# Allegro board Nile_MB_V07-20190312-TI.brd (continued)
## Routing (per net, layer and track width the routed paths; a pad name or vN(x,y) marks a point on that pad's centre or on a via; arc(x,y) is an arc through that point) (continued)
VREG_HUB_3P3: length 46.5
  INNER LAYER 3 w0.3: v3(7.98,11.68) 9.68,11.68 v3(9.83,11.53)
  INNER LAYER 5 w0.3: v3(16.63,12.08) 16.63,12.18 15.61,12.18 15.23,11.8 15.11,11.8 15.11,11.8 14.76,11.8 14.72,11.76 14.46,11.76 13.93,11.23 10.38,11.23 10.08,11.53 v3(9.83,11.53)
  INNER LAYER 8 w0.25: 9.63,11.58 9.63,12.05 9.63,12.05 9.63,12.65 9.71,12.73 9.71,13.26 10.06,13.61 10.06,13.66 v1(10.28,13.88) ; 9.71,11.08 9.71,10.83 9.58,10.71 v1(9.58,10.42)
  INNER LAYER 8 w0.3: v1(15.98,15.18) 15.63,14.83 15.02,14.83 v1(14.15,13.96) 13.73,14.38 v1(11.78,14.38) ; v3(7.98,11.68) 7.83,11.83 7.83,12.41 9.33,13.91 9.33,14.43 v1(9.78,14.88) ; v2(10.83,15.88) 10.88,15.88 10.96,15.96 10.96,15.99 11.68,16.71 v1(11.68,17.78) ; v3(16.63,12.08) 16.58,12.03 v1(16.58,11.63) ; 9.63,11.58 9.68,11.53 v3(9.83,11.53) 9.71,11.41 9.71,11.08
  INNER LAYER 9 w0.22: v1(10.28,16.38) 10.78,15.88 v2(10.83,15.88)
  INNER LAYER 9 w0.3: v1(13.33,17.83) 13.33,17.93 12.98,18.28 11.85,18.28 v1(11.83,18.27) 12.03,18.07 12.03,17.23 11.28,16.48 v1(11.28,16.38) ; v1(9.38,18.27) 9.38,18.43 9.6,18.65 11.02,18.65 11.23,18.43 v1(11.23,18.27)
  BOTTOM w0.076: 16,13.91 15.97,13.94 R6683.1 ; 16,13.31 15.97,13.34 R6679.1 ; 16,12.73 16,12.78 15.97,12.76 R6686.2 ; R6690.2 8.78,18.9 ; 16,15.18 v1(15.98,15.18) R6680.1 ; R6676.2 15.97,14.57 16,14.54 ; 16,12.14 15.97,12.17 R6684.1 ; R6689.2 15.98,15.77 ; R479.2 16,11.48
  BOTTOM w0.15: 8.78,18.9 8.83,18.9 9.06,18.67 9.06,18.63 9.06,18.63 9.06,18.58 9.11,18.53 9.11,18.46 9.3,18.27 v1(9.38,18.27)
  BOTTOM w0.22: v1(9.38,18.27) 9.38,17.88 9.78,17.48 U6838.A7
  BOTTOM w0.3: 16,12.78 16,15.18 ; v1(13.33,17.83) 13.76,17.41 13.76,17.09 14.12,16.73 B33.1 14.83,16.73 14.9,16.8 14.9,16.7 15.2,16.4 ; 15.2,16.4 15.62,16.4 16,16.02 16,15.78 15.98,15.77 v1(15.98,15.18) ; 15.2,16.4 15.17,16.4 15.03,16.53 15.03,16.94 C6370.1 ; B32.2 v1(16.58,11.63) 16.15,11.63 16,11.48 16,12.73 ; v1(11.68,17.78) 11.83,17.93 v1(11.83,18.27) v1(11.23,18.27)
VREG_L3A_1P3: length 16.9
  INNER LAYER 8 w0.3: 23.64,16.4 v1(23.73,16.49) 23.74,16.49 23.88,16.63 ; 23.64,16.4 23.54,16.3 v1(23.54,16.25) ; 23.64,16.4 v1(23.27,16.4)
  INNER LAYER 8 w0.6: 35.37,10.9 32.51,13.76 32.51,15.81 30.75,17.58 24.51,17.58 23.88,16.95 23.88,16.63
VREG_L7A_0P8:
  vias: v7(54.79,29.46) v12(54.9,29.17) v12(55.15,29.18) v12(55.39,29.19)
VREG_L8A_1P8: length 29.9
  TOP w0.2: v5(39,27.96) 39.5,27.46
  TOP w0.25: 38.5,27.96 v5(39,27.96)
  TOP w0.3: v6(38,24.46) v6(38.5,24.46) v6(39,24.46)
  TOP w0.305: v6(39,24.96) v6(39,24.46) ; 39.5,27.46 40,27.46
  INNER LAYER 2 w0.3: v6(37.91,28.26) 38.2,28.26 v5(38.5,27.96)
  INNER LAYER 2 w0.5: v5(39,27.96) 38.52,27.96 v6(38.47,27.92)
  INNER LAYER 3 w0.3: v3(37.67,24.62) 37.83,24.46 v6(38,24.46) ; 37.51,28.26 v6(37.91,28.26) 37.91,28.12 38.11,27.92 ; 37.51,28.26 37.51,28.26 v3(37.41,28.36) ; 37.51,28.26 37.85,27.92 38.11,27.92 ; 38.11,27.92 v6(38.47,27.92) ; v6(38,24.46) 37.89,24.35 v3(37.89,24.15) ; v6(38,24.46) v6(38.5,24.46) ; v6(39,24.96) v6(39,24.46)
  INNER LAYER 7 w0.5: v3(37.89,24.15) 37.89,24.4 v3(37.67,24.62) 37.24,24.62 36.79,25.07 36.79,27.19 36.94,27.34 36.94,27.71 37.41,28.18 v3(37.41,28.36)
  INNER LAYER 7 w0.6: v3(37.41,28.36) 37.41,28.66 37.27,28.8 37.27,34.64 37.28,34.65 37.28,35.29 41.31,39.32
  INNER LAYER 8 w0.3: v3(37.67,24.62) 37.67,24.5 v1(37.49,24.31) 37.73,24.31 v3(37.89,24.15) 38.11,24.37 v1(38.35,24.37)
  INNER LAYER 8 w0.5: v3(37.41,28.36) 37.46,28.31 37.46,27.85 v1(37.5,27.82)
  BOTTOM w0.076: C128.1 38.37,27.84
  BOTTOM w0.3: v1(37.5,27.82) 38.35,27.82 38.37,27.84 ; v1(38.35,24.37) 37.55,24.37 v1(37.49,24.31)
VREG_L9A_1P8: length 64.5
  INNER LAYER 5 w0.25: v3(18.36,41.88) 18.66,41.58 19.53,41.58 19.71,41.41 31.95,41.41 32.26,41.72 39.57,41.72 39.97,42.13
  INNER LAYER 6 w0.127: v7(25.71,10.85) 25.4,10.54 24.8,10.54 24.64,10.38 21.98,10.38 21.98,10.38 v7(21.08,10.38)
  INNER LAYER 7 w0.25: v7(21.23,14.32) 21.23,14.6 21.66,15.03 21.66,33.56 18.63,36.6 18.63,41.69 18.43,41.88 v3(18.36,41.88)
  INNER LAYER 8 w0.127: v7(25.71,10.85) 25.82,10.96 25.83,10.96 25.83,10.61 v8(25.8,10.59)
  INNER LAYER 8 w0.25: v1(21.45,10.38) v7(21.08,10.38)
  INNER LAYER 8 w0.3: v1(21,14.01) 21.23,14.24 v7(21.23,14.32)
  INNER LAYER 9 w0.25: v1(21.68,16.46) 21.42,16.46 v1(20.89,15.93)
  BOTTOM w0.064: U18.32 25.81,10.59 v8(25.8,10.59)
  BOTTOM w0.25: v1(20.89,15.93) 20.89,14.13 v1(21,14.01) 21,13.97 20.95,13.92 20.95,12.32 21.16,12.11 21.16,12.08 21.28,11.96 21.31,11.96 21.53,11.74 C269.1
  BOTTOM w0.4: v1(21.45,10.38) 21.34,10.49 21.58,10.74 C269.1
VREG_L10A_1P8_RES:
  vias: v7(56.75,30.51) v7(57.01,30.76) v7(57.28,30.51) v8(57.63,30.38) v8(57.84,30.3)
VREG_L13A_1P8: length 71
  TOP w0.076: 39.1,17.9 39.11,17.88 C122.1
  TOP w0.25: 39,20.46 39,19.81 39.54,19.27 39.54,18.09 39.74,17.9 39.1,17.9 38.5,18.49 38.5,20.46 ; 39,31.46 39,32.76 39.91,33.66 v6(39.91,34.65) v6(39.25,34.65) 39.25,33.57 38.5,32.83 38.5,31.96
  TOP w0.3: 39.3,34.66 39.9,34.66 v6(39.91,34.65) ; 39.74,17.9 39.74,17.81 v6(39.74,17.8)
  TOP w0.305: 39,20.96 39,20.46
  INNER LAYER 3 w0.3: v6(39.74,17.8) 39.74,17.9 40.14,18.3 40.52,18.3 41.89,19.67
  INNER LAYER 3 w0.35: v6(39.25,34.65) 39.25,34.48 v7(39.4,34.32) ; v6(39.91,34.65) v7(39.91,34.3)
  INNER LAYER 4 w0.3: v7(47.1,34) 47.1,34 ; 47.1,34 47.09,33.99 ; 47.1,34 47.09,34 46.87,34.22 v3(46.87,34.25)
  INNER LAYER 5 w0.3: v7(39.4,34.32) 39.42,34.3 v7(39.91,34.3) ; v3(22.1,11.72) 22.5,12.12 22.5,14.12 23.73,15.35 26.37,15.35 27.81,13.91 v7(27.91,13.91)
  INNER LAYER 5 w0.5: 41.69,33.97 41.63,33.9 40.31,33.9 v7(39.91,34.3)
  INNER LAYER 6 w0.5: v7(39.4,34.32) 39.42,34.3 v7(39.91,34.3)
  INNER LAYER 7 w0.3: v7(39.4,34.32) 39.81,33.92 ; 39.91,33.92 v7(39.91,34.3)
  INNER LAYER 7 w0.5: 39.81,33.92 39.91,33.92
  INNER LAYER 8 w0.25: v1(27.65,13.62) 27.65,13.65 v7(27.91,13.91)
  INNER LAYER 8 w0.3: v1(22.39,11.72) v3(22.1,11.72) ; 46.78,34.31 46.78,34.32 ; v2(18.73,12.68) 18.76,12.68 18.91,12.53 18.91,10.01 v1(18.08,9.18) ; v1(41.61,23.3) 41.44,23.47 40.42,23.47 40.12,23.77 39.32,23.77 39.17,23.92 38.96,23.92 38.77,23.73 37.72,23.73 37.7,23.76 v2(36.21,23.76)
  INNER LAYER 8 w0.5: 41.61,23.29 v1(41.61,23.3)
  INNER LAYER 9 w0.3: v2(36.21,23.76) 36.05,23.6 34.39,23.6 v8(34.36,23.57) ; v1(29.03,15.65) 29.03,15.92 v1(29.02,15.93) 29.02,15.95 29,15.97 ; v1(22.39,11.72) 22.39,11.71 21.96,11.71 21.83,11.57 21.4,11.57 20.66,12.32 19.66,12.32 19.56,12.42 19.01,12.42 18.82,12.61 18.82,12.68 v2(18.73,12.68) 18.73,12.68 v1(18.28,12.68)
  INNER LAYER 9 w0.4: 29,15.97 28.89,16.08 29.89,17.08 30.24,17.08 30.27,17.12 30.58,17.12 30.74,16.96 31.46,16.96 31.83,16.59 32.42,16.59 32.69,16.86 34.41,16.86 35.26,17.71 35.26,22.06 34.81,22.51 34.81,23.11 v8(34.36,23.57)
  BOTTOM w0.076: 26.83,12.1 26.8,12.13
  BOTTOM w0.178: U18.56 26.83,12.1
  BOTTOM w0.2: U18.56 26.83,12.3 26.81,12.32
  BOTTOM w0.3: v8(34.36,23.57) 34.22,23.43 32.14,23.43 31.82,23.75 U11.5 ; 26.81,12.32 26.81,12.41 27.65,13.25 v1(27.65,13.62) 27.8,13.62 28.07,13.88 28.07,13.89 28.29,14.11 28.3,14.11 28.97,14.79 28.97,15.36
  BOTTOM w0.4: 28.97,15.36 29.01,15.39 C262.1
VREG_L19A_3P0: length 13.2
  INNER LAYER 3 w0.3: v6(38,26.96) v6(38,26.46) v6(38,25.96) 37.72,25.96 37.45,26.23 v3(37.45,26.43)
  INNER LAYER 3 w0.5: v3(37.71,27.15) 37.9,26.96 v6(38,26.96)
  INNER LAYER 8 w0.5: v3(37.45,26.43) 37.47,26.45 v1(37.47,26.83) 37.47,26.91 v3(37.71,27.15)
  INNER LAYER 8 w0.6: 40.35,39.34 39.73,38.72 v1(39.03,38.72)
  BOTTOM w0.3: C124.1 37.5,26.82 v1(37.5,25.9) ; C124.1 v1(37.47,26.83) ; C124.1 37.63,26.97 v1(38.33,26.97) ; 39.02,35.34 38.44,35.34 38.33,35.23 ; 39.03,37.84 39.06,37.81 39.06,36.71 38.33,35.97
  BOTTOM w0.5: 38.33,34.87 v1(38.33,33.01)
  BOTTOM w0.6: v1(39.03,38.72) 39.03,37.84 ; 38.33,34.87 38.33,35.97
  vias: v1(37.96,33.28) v1(37.96,32.98) v1(37.99,26.95) v1(38.01,26.59) v1(37.92,26.26) v1(38.31,33.31) v1(38.7,38.92) v1(38.69,33.32) v1(38.66,33) v1(38.74,38.49) v1(39,39.15) v1(39.1,38.35) v1(39.03,33.28) v1(39.02,33.01) v1(39.39,39.19) v1(39.47,38.87) v1(39.44,38.53) v2(37.99,26.95) v2(38.01,26.59) v2(37.92,26.26) v2(38.7,38.92) v2(38.74,38.49) v2(39,39.15) v2(39.1,38.35) v2(39.39,39.19) v2(39.47,38.87) v2(39.44,38.53)
VREG_S1C_S4C_0P752: length 3
  BOTTOM w0.3: C232.1 36.99,21.59
  BOTTOM w1: 29.16,20.84 30.67,20.84 30.78,20.74 32.08,20.74
VREG_S2C_1P125: length 55.4
  TOP w0.076: 41.62,17.86 41.65,17.83 v6(41.65,17.78) ; 41.42,19.98 41.42,19.92 ; 41.95,25.46 42,25.46
  TOP w0.2: 41.2,32.34 v6(41.2,34.65) ; 41.12,31.46 42,31.46 ; 40,31.46 40.33,31.46
  TOP w0.25: v6(41.82,34.65) 41.82,33.36 41.57,33.11 41.57,31.54 41.65,31.46 ; 41.95,25.46 41.62,25.46 41.62,25.46 ; 41.42,19.98 41.62,19.78 41.62,17.86
  TOP w0.254: 41.29,27.9 41.14,27.9 ; 41.29,27.9 41.32,27.9 41.38,27.96 41.44,28.02 41.44,31.14 41.12,31.46 ; 41.29,27.9 41.44,27.74 ; 41.44,25.28 41.62,25.46 ; 41.44,25.28 41.44,23.6 ; 41.44,25.28 41.44,26.7 ; 41.7,26.96 41.44,26.7 ; 41.44,26.7 41.44,27.74 ; 41.42,19.92 41.27,20.07 41.27,20.92 41.22,20.96 ; 41.44,23.6 41.58,23.46 ; 41.44,23.6 41.13,23.29 41.13,21.72 41.18,21.66 41.18,21.33 41.13,21.27 41.13,21.24 41.31,21.05 ; 41.44,27.74 41.42,27.74 ; 41.22,20.96 40.45,20.96 ; 41.22,20.96 41.31,21.05 ; 41.31,21.05 41.37,21.05 41.46,20.96 ; 39.5,31.46 40,31.46 ; 40,27.96 v6(40.9,27.96)
  TOP w0.3: 41.44,24.44 40.06,24.44 v6(40.01,24.49) 40.01,24.47 40,24.46 ; 39.5,20.96 40,20.96 ; 41.44,28.91 41.5,28.96 ; 41.12,31.46 40,31.46 ; v6(41.82,34.65) v6(41.2,34.65)
  TOP w0.305: 40,20.96 40.45,20.96
  TOP w0.4: 41.44,26.96 41.45,26.96
  INNER LAYER 3 w0.3: v6(41.2,34.65) 41.2,34.62 41.36,34.46 v7(41.53,34.46) 41.6,34.46 41.79,34.65 v6(41.82,34.65) ; 41.65,18.15 v6(41.65,17.78) ; v3(40.34,24.55) 40.32,24.55 40.31,24.56 40.08,24.56 v6(40.01,24.49) ; v3(40.23,27.51) 40.23,27.5 v6(40.54,27.5)
  INNER LAYER 3 w0.35: v7(41.53,34.46) 41.59,34.4 41.59,33.91 41.83,33.67
  INNER LAYER 8 w0.25: 41.61,24.9 41.34,24.9
  INNER LAYER 8 w0.3: v1(41.41,24.89) 41.38,24.92 v1(41.06,24.92) 41.04,24.9 40.9,24.9 40.87,24.87 40.73,24.87 ; v3(41.04,24.56) 41.04,24.55 v3(40.34,24.55) ; v3(41.04,24.56) 40.96,24.64 40.95,24.64 40.79,24.81 40.79,24.82 40.73,24.87 ; v3(41.04,24.56) 41.34,24.86 41.34,24.9 ; 40.73,24.87 v1(40.72,24.87) ; 41.11,27.67 41.16,27.62 41.16,27.64 41.17,27.65 41.19,27.63 41.19,27.51 41.21,27.49 41.21,27.32 ; 41.11,27.67 41.1,27.68 ; 41.11,27.67 v3(41.11,27.68)
  INNER LAYER 8 w0.4: 41.21,27.32 40.87,27.32 v1(40.66,27.53) 40.4,27.79 40.4,28.83 40.07,29.17 ; 40.07,29.17 38.16,29.17 36.37,30.95 34.6,30.95 34.41,31.15 v1(32.41,31.15) ; 40.07,29.17 39.77,29.46
  BOTTOM w0.076: C143.1 40.79,26.93
  BOTTOM w0.25: 40.79,25.97 40.89,26.08 40.89,26.82 40.79,26.93 ; 40.69,24.97 40.69,25.34 40.71,25.36 C152.1
  BOTTOM w0.3: L9.2 29.56,31 C225.1 29.83,31.1 C147.1 32.2,31.1 C148.1 v1(32.41,31.15) ; C152.1 40.79,25.97 40.79,26.93 ; 40.69,24.97 40.69,24.88 40.79,24.77 40.79,24.54 40.91,24.42 R60.1
  BOTTOM w0.4: v1(40.66,27.53) 40.79,27.41 40.79,26.93
  vias: v1(29.58,31.28) v1(29.77,31.03) v1(29.9,31.3) v1(30.4,31.12) v1(30.45,31.42) v1(30.75,31.14) v1(30.99,30.93) v1(31.13,31.22) v1(31.63,31.44) v1(31.64,31.08) v1(32.08,31.28) v1(32.12,30.98) v1(41.24,25.25) v2(29.58,31.28) v2(29.77,31.03) v2(29.9,31.3) v2(30.4,31.12) v2(30.45,31.42) v2(30.75,31.14) v2(30.99,30.93) v2(31.13,31.22) v2(31.63,31.44) v2(31.64,31.08) v2(32.08,31.28) v2(32.12,30.98) v2(41.24,25.25) v3(39.87,27.63) v5(40.01,27.92) v5(40.47,27.89) v5(40.77,27.69) v5(40.96,27.42) v5(41.27,27.32) v6(40.01,27.92) v6(40.47,27.89) v6(40.77,27.69) v6(40.96,27.42) v6(41.27,27.32)
VREG_S3A_0P6: length 18.2
  TOP w0.076: 40.36,17.8 40.36,17.8 v6(40.37,17.79)
  TOP w0.15: R4656.1 41.6,16 41.04,16 v6(41.01,15.98) ; 40.43,17.87 40.36,17.8
  TOP w0.25: 40,20.46 41.01,19.46 41.01,17.87 40.4,17.87 40.41,17.89 40.41,19.07 39.5,19.98 39.5,20.46 ; 40.52,33.34 40.52,32.77 40.04,32.3 40.04,32 40,31.96 ; 40.52,33.34 v6(40.52,34.65) ; 40.52,33.34 39.5,32.33 39.5,31.96
  TOP w0.3: 41.01,17.87 v6(41.01,17.83)
  INNER LAYER 3 w0.3: 41.59,17.29 41.57,17.27 ; 41.57,17.27 41.57,16.53 v6(41.01,15.98) ; 41.57,17.27 v6(41.01,17.83) ; v6(40.52,34.65) 40.52,34.44 40.59,34.36 v7(40.71,34.36)
  INNER LAYER 7 w0.3: 40.89,35.2 40.71,35.01
  INNER LAYER 7 w0.4: v7(40.71,34.36) 40.71,35.23 40.78,35.31 40.89,35.2
  INNER LAYER 8 w0.3: v7(40.71,34.36) 40.68,34.33 40.68,33.11 40.29,32.72 v1(40.15,32.72)
VREG_S3C_0P752: length 2
  BOTTOM w0.5: L10.2 32.6,29.85 33.1,29.35 33.81,29.35 C228.1
  vias: v7(53.18,28.93)
VREG_S5A_1P0_VIN_GR2:
  vias: v5(66.06,30.75)
VREG_WL_3P3: length 2.7
  INNER LAYER 9 w0.4: v1(21.29,15.31) 21.29,15.19 21.53,14.96 21.86,14.96 22.1,15.2 22.1,15.3 v1(22.1,15.3) 22.11,15.29 v1(22.49,15.29)
  BOTTOM w0.076: U19.4 v1(21.29,15.31)
  BOTTOM w0.4: R102.1 21.83,13.62 22.27,14.06 22.27,14.47
VSNS_CX_M: length 13.1
  INNER LAYER 8 w0.076: v1(41.36,22.67) 41.28,22.59 41.26,22.59 40.78,23.06 40.25,23.06 39.99,23.32 35.29,23.32 35.25,23.36 35.25,23.37 34.75,23.87 34.75,24.1 34.75,24.11 34.75,24.23 34.45,24.53 34.34,24.53 34.33,24.54 33.4,24.54 33.04,24.17 31.63,24.17 31.08,24.72 v1(31.08,25.05)
  INNER LAYER 9 w0.076: v1(31.08,25.05) 30.57,25.05 30.33,25.29 v1(30.33,25.3)
  BOTTOM w0.15: v1(41.36,22.67) 41.39,22.64 41.52,22.64
VSNS_CX_P: length 13.6
  INNER LAYER 8 w0.076: v1(41.32,22.31) 40.72,22.91 40.19,22.91 39.93,23.17 35.23,23.17 34.59,23.81 34.59,23.94 34.6,23.94 34.6,24.17 34.4,24.37 33.47,24.37 33.1,24.01 31.2,24.01 31.14,24.07 31.12,24.07 30.15,25.05 v8(30.09,25.05)
  BOTTOM w0.076: 30.27,25.05 U11.30
  BOTTOM w0.102: 30.27,25.05 30.26,25.05 v8(30.09,25.05)
  BOTTOM w0.15: 41.5,22.31 v1(41.32,22.31)
VSNS_DDR_VDD2_M: length 15.6
  INNER LAYER 8 w0.076: v1(30.09,25.55) 30.07,25.56 29.69,25.56 29.48,25.35 29.48,24.31 29.81,23.98 30.55,23.98 30.94,23.59 30.96,23.59 31.02,23.53 33.52,23.53 34.46,22.59 34.87,22.17 40.06,22.17 40.11,22.13 v1(40.31,22.13)
  BOTTOM w0.076: v1(40.31,22.13) 40.41,22.23 R61.2
  BOTTOM w0.4: R61.2 40.41,24.21
VSNS_DDR_VDD2_P: length 14.7
  INNER LAYER 8 w0.076: v1(29.83,25.3) 29.64,25.11 29.64,24.37 29.87,24.14 30.61,24.14 31,23.75 31.02,23.75 31.08,23.69 33.57,23.69 34.94,22.33 40.1,22.33 40.14,22.37 40.6,22.37 v1(40.71,22.25)
  BOTTOM w0.076: R60.2 40.91,23.65 40.62,23.36 40.62,22.34 v1(40.71,22.25)
VSNS_GFX_M: length 9.8
  INNER LAYER 8 w0.076: v9(33.27,30.64) 33.27,30.46 33.17,30.36 33.17,29.97 33.05,29.85 33.05,28.3 31.32,26.56 31.32,26.16 31.3,26.15 31.3,26.14 31.27,26.1 31.27,26.05 31.27,25.92 31,25.66 31,25.62 v8(31.08,25.54)
  BOTTOM w0.076: v9(33.27,30.64) 33.35,30.56 35.64,30.56 36.58,31.5
  BOTTOM w0.15: U11.42 v8(31.08,25.54)
VSNS_GFX_P: length 10.2
  INNER LAYER 8 w0.076: v8(30.58,25.54) 30.66,25.54 30.66,25.61 30.74,25.61 31.12,25.98 31.12,26.17 31.16,26.22 31.16,26.64 32.89,28.37 32.89,29.91 32.97,29.99 v1(32.97,30.51)
  BOTTOM w0.076: 33.76,30.4 35.71,30.4 36.65,31.35 ; 33.76,30.4 33.76,30.41 ; 33.76,30.4 33.08,30.4 v1(32.97,30.51)
WCN_RFCLK1: length 9.5
  INNER LAYER 5 w0.076: 34.88,10.59 29.78,15.69 27.97,15.69 v7(27.9,15.62)
  INNER LAYER 8 w0.076: v1(27.95,15.25) 27.95,15.56 v7(27.9,15.62)
WCSS_CH0_CMD_CLK: length 17.2
  INNER LAYER 3 w0.076: 35.77,8.28 35.13,7.64 30.77,7.64 30.68,7.55 v3(30.68,7.53)
  INNER LAYER 6 w0.076: v7(23.17,10.98) 23.33,11.13 24.73,11.13 24.77,11.17 25.9,11.17 26.18,10.89 26.18,10.25 28.75,7.68 28.77,7.68 29.22,7.23 30.38,7.23 v3(30.68,7.53)
  INNER LAYER 8 w0.076: v7(23.17,10.98) 23.24,10.98 23.36,11.09 23.49,11.09 23.5,11.08 23.76,11.08 23.77,11.09 24.26,11.09 24.27,11.09 24.31,11.09 24.37,11.15 24.4,11.15 v8(24.4,11.14)
  BOTTOM w0.076: U18.9 24.75,11.3 24.71,11.27 24.53,11.27 v8(24.4,11.14)
WCSS_CH0_CMD_DATA: length 18.2
  INNER LAYER 3 w0.076: v3(30.13,7.63) 30.38,7.88 31.08,7.88 31.17,7.8 35.08,7.8 35.71,8.43
  INNER LAYER 6 w0.076: v3(30.13,7.63) 29.03,7.63 28.84,7.83 28.81,7.83 26.33,10.31 26.33,10.96 25.96,11.33 23.68,11.33 23.4,11.62 v7(23.08,11.62)
  INNER LAYER 8 w0.076: v7(23.08,11.62) 23.07,11.62 23.07,11.71 23.75,12.39 23.75,13.05 23.86,13.16 23.86,13.28 24.1,13.52 24.1,13.92 23.97,14.05 v1(23.97,14.27)
WL_BT_COEX_CLK: length 9.1
  INNER LAYER 5 w0.076: 35.1,9.12 34.97,9.12 34.43,9.66 34.37,9.66 32.31,11.72 31.37,11.72 v7(30.94,12.15)
  INNER LAYER 8 w0.076: v7(30.94,12.15) 30.51,12.15 30.45,12.21 29.06,12.21 28.71,11.87 28.4,11.87 28.4,11.89 v9(28.41,11.89)
  BOTTOM w0.076: U18.76 27.69,11.68 28.07,11.68 28.23,11.84 28.37,11.84 28.4,11.87 28.4,11.89 v9(28.41,11.89)
WL_BT_COEX_DATA: length 8.9
  INNER LAYER 5 w0.076: v7(30.13,11.75) 30.13,11.71 30.44,11.4 32.2,11.4 34.25,9.35 34.29,9.35 34.81,8.83 34.81,8.83 34.84,8.8
  INNER LAYER 8 w0.076: v7(30.13,11.75) 30.13,11.66 30.12,11.65 29.45,11.65 v9(29.45,11.69)
  BOTTOM w0.076: v9(29.45,11.69) 29.45,11.61 29.27,11.44 28.53,11.44 28.45,11.36 27.87,11.36 27.81,11.3 U18.77
WL_BT_RFIO_2G_CH0: length 6
  BOTTOM w0.076: C287.1 29.69,6.12
  BOTTOM w0.12: 29.69,6.12 29.07,6.12 L26.2 29.05,6.12 27.15,6.12 arc(26.33,6.46) 25.98,7.28 25.98,8.57 arc(26.01,8.71) U18.42
WL_CH0_BB_I_M: length 21.1
  TOP w0.06: v15(42.26,15.97) 42.26,15.96 C6289.1
  INNER LAYER 3 w0.075: 43.08,16.68 42.64,16.24 42.53,16.24 v15(42.26,15.97) 42.26,15.87 40.77,14.38 ; 38.48,13.24 38.87,13.24 38.96,13.15 38.96,12.57 38.14,11.75
  INNER LAYER 3 w0.076: 38.14,11.75 31.37,11.75 v7(30.03,10.41) ; 38.48,13.24 38.19,13.53 38.19,14.09 38.47,14.37 40.77,14.37 40.77,14.38
  INNER LAYER 8 w0.076: v9(29.18,9.98) 29.57,9.98 29.74,10.16 29.93,10.16 30.03,10.26 v7(30.03,10.41)
  BOTTOM w0.076: v9(29.18,9.98) 29.1,9.91 28.82,9.91 28.74,9.83 27.95,9.83 27.81,9.97 27.8,9.97 27.71,10.06 U18.73
WL_CH0_BB_I_P: length 21.5
  TOP w0.06: 42.87,15.96 42.87,15.96 42.84,15.99 42.69,15.99 v15(42.68,15.99)
  INNER LAYER 3 w0.075: 40.86,14.17 40.88,14.17 41.16,14.46
  INNER LAYER 3 w0.076: 43.16,16.47 42.68,15.99 v15(42.68,15.99) 41.16,14.46 41.16,14.46 ; v7(30.58,10.39) 30.58,10.64 31.47,11.54 38.22,11.54 39.17,12.48 39.17,13.23 38.95,13.45 38.57,13.45 38.39,13.62 38.39,14.01 38.55,14.17 39.23,14.17 arc(39.29,14.14) 39.32,14.08 arc(39.41,13.99) 39.5,14.08 arc(39.58,14.17) 39.67,14.08 arc(39.76,13.99) 39.85,14.08 arc(39.88,14.14) 39.94,14.17 40.85,14.17 40.86,14.17
  INNER LAYER 8 w0.076: v7(30.58,10.39) 30.58,10.37 30.43,10.37 30.01,9.95 29.82,9.95 29.65,9.78 29.35,9.78 29.23,9.66 v9(29.17,9.66)
  BOTTOM w0.076: U18.80 27.67,9.82 27.72,9.77 27.73,9.77 27.87,9.63 28.83,9.63 28.9,9.7 29.05,9.7 29.09,9.66 v9(29.17,9.66)
WL_CH0_BB_Q_M: length 14.5
  INNER LAYER 3 w0.076: v7(32.76,9.42) 32.9,9.56 40.37,9.56
  INNER LAYER 8 w0.076: v7(32.76,9.42) 32.67,9.51 32.67,9.82 31.41,11.08 29.64,11.08 29.04,10.49 28.8,10.49 v9(28.56,10.25)
  BOTTOM w0.076: v9(28.56,10.25) 28.51,10.2 28.09,10.2 27.96,10.33 27.95,10.33 27.87,10.41 27.87,10.41 27.71,10.57 27.34,10.57 U18.72
WL_CH0_BB_Q_P: length 21.9
  INNER LAYER 3 w0.076: v7(32.3,9.48) 32.39,9.48 32.45,9.54 32.45,9.55 32.66,9.76 40.27,9.76 45.13,14.63 45.13,14.63
  INNER LAYER 8 w0.076: v7(32.3,9.48) 32.45,9.63 32.45,9.74 32.16,10.04 arc(32.09,10.06) 32.03,10.04 31.97,9.98 arc(31.85,9.98) 31.85,10.1 31.91,10.16 arc(31.91,10.29) 31.78,10.29 31.72,10.23 arc(31.6,10.23) 31.6,10.35 31.66,10.41 arc(31.68,10.47) 31.66,10.54 31.44,10.75 31.44,10.75 31.32,10.87 31.32,10.88 29.72,10.88 29.03,10.19 28.92,10.19 v9(28.89,10.22)
  BOTTOM w0.076: v9(28.89,10.22) 28.89,10.2 28.68,9.99 28.01,9.99 27.87,10.13 27.86,10.13 27.78,10.21 27.78,10.21 27.68,10.31 U18.79
WL_CH1_BB_I_M: length 15.4
  INNER LAYER 3 w0.06: v7(28.66,9.65) 28.64,9.69
  INNER LAYER 3 w0.076: 38.45,10.86 31.98,10.86 30.72,9.6 29.42,9.6 29.31,9.71 29.3,9.71 29.17,9.84 29.17,10.93 29.07,11.03 28.84,11.03 28.66,10.85 28.66,9.93 28.66,9.92 28.66,9.7 28.64,9.69 ; v7(28.66,9.65) 28.66,9.7
  INNER LAYER 8 w0.06: 26.91,9.98 26.9,9.99
  INNER LAYER 8 w0.076: v7(28.66,9.65) 28.66,9.74 28.31,10.09 28.05,10.09 27.95,9.99 27.58,9.99 ; 27.58,9.99 27.58,9.98 27.37,9.98 ; 27.58,9.99 27.38,9.99 27.37,9.98 ; 27.07,9.98 26.91,9.98 ; 27.07,9.98 27.1,9.96 27.34,9.96 27.37,9.98 ; 27.07,9.98 27.06,9.99 26.9,9.99 26.85,10.05 v8(26.83,10.05)
WL_CH1_BB_I_P: length 14.7
  INNER LAYER 3 w0.076: v7(28.19,9.75) 28.45,10.01 28.45,10.93 28.66,11.14 28.66,11.14 28.76,11.24 29.15,11.24 29.38,11.01 29.38,9.92 29.49,9.81 30.64,9.81 31.89,11.06 38.37,11.06
  INNER LAYER 8 w0.076: v8(26.58,9.82) 26.62,9.78 26.99,9.78 27.01,9.75 v7(28.19,9.75)
WL_CH1_BB_Q_M: length 20.4
  INNER LAYER 3 w0.076: v7(27.81,10.36) 27.75,10.36 27.75,10.26 27.63,10.13 27.63,9.53 27.65,9.51 27.65,9.5 28.03,9.12 30.68,9.12 32.09,10.53 38.56,10.53 41.62,13.58 42.06,13.58 42.29,13.35 42.41,13.35 42.78,13.73 42.78,14.07 42.67,14.18 42.67,14.64
  INNER LAYER 8 w0.076: v8(26.83,10.56) 26.85,10.54 26.89,10.59 27.59,10.59 v7(27.81,10.36)
WL_CH1_BB_Q_P: length 20.6
  INNER LAYER 3 w0.076: v7(27.28,10.28) 27.42,10.14 27.42,9.44 27.95,8.91 30.76,8.91 32.17,10.32 38.64,10.32 38.77,10.45 38.77,10.45 41.7,13.38 41.97,13.38 42.2,13.15 42.33,13.15 42.49,13.15 43.06,13.72 43.06,14.08 42.87,14.27 42.87,14.55
  INNER LAYER 8 w0.076: v8(26.58,10.31) 27.22,10.31 27.24,10.28 v7(27.28,10.28)
WL_RFI_5G_CH0: length 1.6
  BOTTOM w0.076: R119.2 28.47,8.5
  BOTTOM w0.1: U18.75 27.33,8.84 arc(27.42,8.6) 27.66,8.5 28.47,8.5
WL_RFO_5G_CH0: length 2.2
  BOTTOM w0.076: R118.1 28,7.57 ; R116.2 28.59,7.57
  BOTTOM w0.12: 28.59,7.57 28,7.57 28,7.58 27.31,8.28 arc(27.14,8.53) U18.68
WLAN_SW_CTRL: length 17.3
  INNER LAYER 5 w0.076: v7(24.84,15.99) 25.2,16.35 26.33,16.35 26.6,16.08 27.67,16.08 27.83,16.23 28.47,16.23 28.59,16.12 29.68,16.12 29.68,16.12 29.83,16.12 35.02,10.93
  INNER LAYER 8 w0.076: v1(24.89,12.87) 24.75,13 24.75,13.12 24.41,13.46 24.41,14.04 24.38,14.06 24.38,14.57 24.31,14.64 24.31,15.17 24.8,15.66 24.8,15.83 24.84,15.87 v7(24.84,15.99)
  BOTTOM w0.076: U18.15 25.35,12.41 v1(24.89,12.87)
N13747238:
  vias: v4(68.89,23.77) v4(69.14,24.02)
N13747596:
  vias: v5(68.46,28.62) v5(68.6,28.33) v5(69.14,26.99)
N13747700:
  vias: v5(65.39,29.12) v5(65.66,29.24) v5(65.65,28.91)
N13749854: length 1.4
  BOTTOM w0.076: C226.1 33.34,23.86
  BOTTOM w0.1: 33.34,23.86 33.13,24.07 32.08,24.07 U11.11
N13749894: length 1.1
  BOTTOM w0.076: C229.1 33.31,25.52
  BOTTOM w0.2: 33.31,25.52 33.15,25.36 32.81,25.36 32.75,25.3 U11.39
N13749950: length 3.4
  BOTTOM w0.076: R87.2 33.62,27.39 33.61,27.39 33.61,26.77 ; R88.1 33.62,26.76 33.62,26.76
  BOTTOM w0.2: U11.71 31.84,26.78 32.16,27.11
  BOTTOM w0.3: 32.16,27.11 32.22,27.17 33.21,27.17 33.61,26.77 33.61,26.76 33.62,26.76 33.62,27.39
N13750348: length 5.3
  INNER LAYER 9 w0.1: v4(30.58,24.06) 30.58,24.2 30.58,24.2 30.58,24.52 30.58,24.52 v4(30.58,24.56)
  INNER LAYER 9 w0.2: v4(30.58,24.06) 30.51,23.99 30.51,23.11 29.86,22.46 29.41,22.46 28.18,23.69 v1(28.18,23.69)
  BOTTOM w0.1: v4(30.58,24.06) v4(30.58,24.56)
  BOTTOM w0.2: v1(28.18,23.69) 28.17,23.71 G15.2
N13750434: length 10.9
  INNER LAYER 9 w0.1: v4(30.58,26.04) v4(30.58,26.54) 30.58,28.19 30.34,28.44
  INNER LAYER 9 w0.3: 30.34,28.44 30.34,28.48 30.01,28.81 v1(29.96,28.81) 28.41,28.81 28.2,28.6 v1(28.2,27.1) 28.2,27.06 v1(28,26.86)
  BOTTOM w0.1: v1(29.96,28.81) 30.01,28.86 30.21,28.86 30.58,28.5 30.58,27.74 30.58,27.74 v4(30.58,26.54) v4(30.58,26.04)
  BOTTOM w0.3: v1(28.2,27.1) 28.2,27.06 v1(28,26.86) C223.2
N13750548: length 3.6
  INNER LAYER 9 w0.1: v4(31.57,26.54) 31.57,26.53 31.57,26.04 v4(31.57,26.04)
  INNER LAYER 9 w0.2: v1(30.88,28.57) 31.35,28.57 32.12,27.81 32.12,27.31 31.97,27.17 31.97,26.94 v4(31.57,26.54)
N13750620: length 4.6
  INNER LAYER 9 w0.15: v4(31.57,24.56) v4(31.57,24.06) 31.57,24.06
  INNER LAYER 9 w0.25: 31.57,24.06 31.66,23.96 31.66,23.83
  INNER LAYER 9 w0.3: v4(31.31,22.51) 31.56,22.51 ; 31.56,22.51 31.61,22.46 32.11,22.46 32.26,22.61 32.26,23.23 31.66,23.83 ; 31.56,22.51 v4(31.31,22.76)
  BOTTOM w0.076: G17.2 31.26,22.07 C230.2
  BOTTOM w0.2: v4(31.31,22.76) 31.33,22.76
  BOTTOM w0.3: 31.33,22.76 31.33,22.07 31.26,22.01 C230.2
N13750716: length 1.8
  INNER LAYER 9 w0.076: v4(30.21,23.61) 30.21,23.76 30.27,23.81
  BOTTOM w0.075: 30.32,23.81 v1(30.32,24.31)
  BOTTOM w0.076: v1(30.09,24.56) v1(30.33,24.31) ; v1(29.79,22.86) 29.52,22.59 29.2,22.59
  vias: v1(29.73,23.16) v1(29.96,23.11) v1(30.06,23.36)
N13750828: length 1.8
  BOTTOM w0.203: 29.43,27.9 29.43,27.89 29.98,27.89 30.33,27.53 30.33,26.8
  vias: v4(29.56,28.05) v4(29.57,27.79) v4(29.95,28.05) v4(29.94,27.79) v4(30.09,26.04) v4(30.32,27.06) v4(30.33,26.78) v4(30.33,26.3)
N13750950: length 3.9
  INNER LAYER 9 w0.2: 31.49,27.25 v1(31.32,27.08) v1(31.32,26.78) 31.32,26.68 31.29,26.65 31.29,26.42 31.32,26.39 v4(31.32,26.29) v1(31.08,26.04)
  BOTTOM w0.076: v4(31.32,26.29) v1(31.32,26.78)
  BOTTOM w0.2: L10.1 32.04,28 ; v4(31.32,26.29) v1(31.08,26.04)
  BOTTOM w0.203: 32.47,27.9 32.39,27.81 32.01,27.81 31.32,27.13
  vias: v1(31.37,27.39) v1(31.56,27.75) v1(31.67,27.39)
N13751070: length 2.4
  BOTTOM w0.076: 32.08,22.59 32.04,22.59 31.32,23.3 U11.4
  BOTTOM w0.1: v1(31.08,24.56) 31.2,24.43 U11.15 U11.4
  vias: v1(31.41,23.46) v1(31.65,23.08) v1(31.84,22.81) v4(31.31,24.31) v4(31.31,23.81)
N13751276: length 1.1
  BOTTOM w0.076: R89.2 33.31,24.91
  BOTTOM w0.2: 33.31,24.91 33.17,24.77 32.35,24.77 U11.28
N13764432: length 1.9
  INNER LAYER 8 w0.076: v9(25.99,13.61) 25.83,13.46 25.83,12.05 26.02,11.86 v8(26.02,11.81)
N13764562: length 5.8
  INNER LAYER 8 w0.06: 26.47,12.17 26.47,12.13 26.46,12.12 26.46,12.01 26.38,11.93 26.38,11.75 26.39,11.74
  INNER LAYER 8 w0.076: 26.39,11.74 26.39,11.55 v8(26.37,11.53) ; 26.47,12.17 26.47,12.42 26.58,12.53 26.58,14.7 v1(26.69,14.82)
  BOTTOM w0.076: C442.2 27.93,15.85 27.93,15.86 ; 26.92,15.64 27.02,15.74 27.11,15.74 ; 26.92,15.64 26.92,15.65 27.12,15.86 27.93,15.86 ; 26.92,15.64 Y1.3 26.83,15.62 26.8,15.59 26.8,14.93 v1(26.69,14.82) ; 27.93,15.86 27.95,15.88
N13764570: length 6.8
  INNER LAYER 8 w0.06: v8(26.09,11.3) 26.09,11.58 26.23,11.73 26.23,12.1 26.32,12.18
  INNER LAYER 8 w0.076: v1(25.93,14.8) 25.95,14.82 26.07,14.82 26.43,14.46 26.43,12.62 26.32,12.51 26.32,12.18
  BOTTOM w0.076: v1(25.93,14.8) 25.92,14.82 25.92,14.84 ; 25.92,14.84 25.92,14.85 25.85,14.92 ; 25.92,14.84 25.94,14.84 26.26,15.17 26.26,16.25 26.04,16.47 Y1.1 25.77,16.49 25.87,16.59 25.97,16.59 25.97,16.6 25.85,16.72 25.75,16.72
N13764650: length 2.2
  BOTTOM w0.076: C279.1 28.59,13.56
  BOTTOM w0.1: U18.69 27.49,12.04 27.56,12.11 27.58,12.11 27.72,12.25 27.72,12.27 28.16,12.71 28.16,13.18 28.54,13.56 28.59,13.56
N13764670: length 1.3
  BOTTOM w0.076: R115.1 29.85,14.19 ; C280.1 29.83,13.56 ; C279.2 29.22,13.56
  BOTTOM w0.1: 29.85,14.19 29.84,14.18 29.84,13.57 29.83,13.56 29.22,13.56
N13764744: length 4.1
  INNER LAYER 8 w0.071: 24.58,11.51 24.92,11.17 24.95,11.17
  INNER LAYER 8 w0.076: v1(24.25,13.12) 24.05,12.92 24.05,12.27 23.82,12.03 23.82,11.64 23.94,11.52 23.94,11.51 24.58,11.51 ; v8(25.35,11.05) 25.14,11.05 25.02,11.17 24.95,11.17
  BOTTOM w0.076: R105.1 23.96,13.64 24,13.59 24,13.42 24.25,13.17 v1(24.25,13.12)
N13765314: length 1.8
  BOTTOM w0.076: U18.10 24.6,10.81 24.51,10.72 23.62,10.72 23.46,10.55 R106.1
N13765772: length 0.9
  BOTTOM w0.076: C6329.2 33.74,8.37
  BOTTOM w0.12: U22.5 33.67,8.44 33.74,8.37
N13765776: length 1.3
  BOTTOM w0.076: C286.1 35.54,8.37 ; L3704.2 34.94,8.37 ; C6329.1 34.37,8.37
  BOTTOM w0.12: 35.54,8.37 35.53,8.38 34.95,8.38 34.94,8.37 34.37,8.37
N13765780: length 1.1
  BOTTOM w0.076: C282.1 31.03,7.58
  BOTTOM w0.12: 31.03,7.58 31.28,7.83 arc(31.57,8.03) U22.1
N13765784: length 1.3
  BOTTOM w0.076: R116.1 29.22,7.57 ; R117.1 29.79,7.57 ; C282.2 30.4,7.58
  BOTTOM w0.12: 29.22,7.57 29.79,7.57 29.81,7.58 30.4,7.58
N13765868: length 1.5
  BOTTOM w0.076: 29.69,8.5 29.7,8.51 C285.1 ; C284.2 30.49,8.72 ; R119.1 29.1,8.5
  BOTTOM w0.12: 29.1,8.5 29.69,8.5 29.7,8.49 29.96,8.49 arc(30.25,8.55) 30.49,8.72
N13766128: length 1.5
  BOTTOM w0.076: C286.2 36.17,8.37 ; L25.2 36.74,8.36
  BOTTOM w0.12: FL1.4 36.2,8.33 36.17,8.37 L25.2
N13766140: length 0.6
  BOTTOM w0.076: R121.1 37.14,7.02
  BOTTOM w0.12: 37.14,7.02 FL1.2
N13766428: length 0.8
  BOTTOM w0.076: C284.1 31.12,8.72
  BOTTOM w0.12: U22.3 31.29,8.79 arc(31.2,8.77) 31.12,8.72
N13766504: length 1.3
  BOTTOM w0.076: C556.1 38.34,7.02 ; R120.1 38.94,7.02
  BOTTOM w0.12: 38.94,7.02 38.87,7.02 38.85,7 38.38,7 38.35,7.03 38.34,7.02 R121.2 37.72,7.02
N13766548: length 1.4
  BOTTOM w0.076: C288.1 34.39,6.27
  BOTTOM w0.12: 34.39,6.27 34.38,6.25 L28.1 33.02,6.25 FL2.4
N13766584: length 1.7
  BOTTOM w0.076: C287.2 30.32,6.12
  BOTTOM w0.12: FL2.1 31.64,6.39 arc(31.32,6.18) L27.1 30.94,6.12 30.32,6.12
N13766616: length 5.1
  TOP w0.12: J3.1 arc(40.56,11.35) 40.64,10.91 40.64,10.17 arc(40.4,8.92) 39.69,7.86 arc(39.63,7.77) v11(39.6,7.67)
  BOTTOM w0.076: R120.2 39.57,7.04
  BOTTOM w0.12: 39.57,7.02 39.57,7.04 39.6,7.08 v11(39.6,7.67)
N13766620: length 2.8
  TOP w0.076: R122.1 38.59,9.01
  TOP w0.12: 38.59,9.01 38.59,9.61 L20.2 arc(38.45,9.81) 38.4,10.04 J3.2
N13766628: length 4
  TOP w0.076: R122.2 38.59,8.39
  TOP w0.12: 38.59,8.39 38.59,7.69 L22.2 arc(38.37,7.55) 38.11,7.5 D3865.1 arc(37.3,7.57) 36.97,7.8 36.02,8.75 arc(35.98,8.81) 35.96,8.88
N13778471: length 4.5
  BOTTOM w0.3: 41.81,41.09 41.14,41.09 41.07,41.16 ; 41.07,41.16 41.05,41.18 40.99,41.11 PS3.1 ; 41.07,41.16 D3707.2
N13780185: length 0.9
  INNER LAYER 9 w0.076: v1(3.77,18.93) 3.89,18.82 3.89,18.8 v1(4.38,18.31)
N13780193: length 5.4
  BOTTOM w0.2: BTTN3.2 2.4,16.72 3.01,16.11 3.01,14.16 2.4,13.55 BTTN3.1
  BOTTOM w0.3: L3711.2 2.5,17.12 BTTN3.2
  vias: v1(2.2,16.95) v1(2.19,16.57) v1(2.18,13.75) v1(2.19,13.34) v1(2.2,12.98) v1(2.21,17.32) v1(2.58,16.58) v1(2.55,13.75) v1(2.58,13.36) v1(2.57,12.98) v1(2.61,17.32) v1(2.62,16.93)
N13780517: length 2.1
  BOTTOM w0.3: D3707.1 41.21,35.64 41.21,33.69
N13780603: length 3.5
  INNER LAYER 9 w0.1: v1(7.31,37.91) 7.26,37.86 4.86,37.86 4.28,37.27 v1(4.28,37.11)
N13780655: length 5
  INNER LAYER 9 w0.1: v1(2.66,38.71) 2.96,39.01 2.96,41.36 v1(2.76,41.56)
  BOTTOM w0.1: BTTN5.2 2.39,41.93 v1(2.76,41.56) ; L3713.2 2.4,38.4 BTTN5.1
  vias: v1(2.13,42.52) v1(2.16,42.07) v1(2.18,41.57) v1(2.16,38.78) v1(2.16,38.33) v1(2.16,37.91) v1(2.59,42.5) v1(2.59,41.96) v1(2.64,38.29) v1(2.63,37.92)
N13781083: length 5.3
  INNER LAYER 9 w0.3: v1(24.43,3.02) 23.96,2.55 22.05,2.55 v1(21.72,2.88)
  BOTTOM w0.076: R288.2 26.31,3.67
  BOTTOM w0.3: BTTN1.4 25.08,3.15 25.6,3.67 26.31,3.67 ; BTTN1.3 21.45,3.15 v1(21.72,2.88)
  vias: v1(21.07,3.22) v1(21.04,2.89) v1(21.34,2.92) v1(21.52,3.25) v1(24.48,3.38) v1(24.82,3.32) v1(24.82,2.98) v1(25.2,3.33) v1(25.23,3)
N13781141: length 5.2
  INNER LAYER 9 w0.1: v1(2.61,29.36) 2.96,29.01 2.96,26.76 2.71,26.51 v1(2.71,26.41)
  BOTTOM w0.1: BTTN6.2 2.26,29.65 2.26,30.81 L3715.2 ; BTTN6.1 2.4,26.1 v1(2.71,26.41)
  vias: v1(2.18,26.21) v1(2.25,29.93) v1(2.21,29.54) v1(2.22,29.1) v1(2.22,25.8) v1(2.22,25.47) v1(2.6,29.03) v1(2.58,26.06) v1(2.59,25.7) v1(2.64,29.92)
N13781157: length 5.1
  INNER LAYER 9 w0.1: v1(3.41,26.46) 3.26,26.61 3.26,29.11 v1(3.51,29.36)
  BOTTOM w0.1: BTTN6.3 3.55,29.66 L3714.2 ; v1(3.41,26.46) 3.7,26.17 BTTN6.4
  vias: v1(3.48,26.06) v1(3.47,25.57) v1(3.54,28.97) v1(3.85,29.3) v1(3.87,26.37) v1(3.9,25.97) v1(3.87,25.58) v1(3.91,28.99)
N13781221: length 4
  INNER LAYER 9 w0.1: v1(4.18,30.81) 4.18,30.2 6.01,28.36 v1(6.76,28.36)
N13788470: length 1.4
  TOP w0.076: U3702.3 33.26,26.59 R4648.1
N13792202: length 3.5
  BOTTOM w0.5: U3704.1 13.97,39.51 13.82,39.66 13.74,39.66 C310.1 12.87,39.88 D3600.1
N13792228: length 1.6
  BOTTOM w0.3: U3704.3 13.98,41.41 13.68,41.7 R413.1
N13800559: length 2.1
  BOTTOM w0.076: C378.1 17.41,26.66 17.4,26.65
  BOTTOM w0.1: U33.3 17.19,26.45 17.4,26.66 17.4,26.65 17.64,26.41 17.65,26.41 17.91,26.15 C377.2
N13800591: length 1.6
  BOTTOM w0.074: C363.1 12.29,29.42 12.43,29.28 12.43,28.53 12.24,28.34 U33.41
  BOTTOM w0.076: C363.1 12.26,29.45 12.24,29.46 12.3,29.52
N13800619: length 1.5
  BOTTOM w0.074: U33.42 12.74,28.38 12.64,28.48 12.64,29.18 C364.1
N13800787: length 6.3
  INNER LAYER 8 w0.3: v1(12.15,20.26) 12.15,20.82 11.93,21.03 10.01,21.03 9.11,20.13 8.38,20.13 8.14,19.89 v1(8.14,19.78)
  BOTTOM w0.25: v1(12.15,20.26) 12.15,20.56 12.24,20.65 U33.20
N13800859: length 0.7
  BOTTOM w0.1: TP25.1 17.06,25.96 16.8,25.96 16.79,25.95 U33.4
N13800863: length 1.9
  BOTTOM w0.076: R194.2 17.46,24.32
  BOTTOM w0.1: U33.5 16.82,25.45 17.46,24.81 17.46,24.32
N13800897: length 3
  BOTTOM w0.076: C376.1 8.18,27.11
  BOTTOM w0.25: 9.16,26.45 U33.34
  BOTTOM w0.3: 9.16,26.45 8.83,26.45 8.18,27.11 8.11,27.05 8.11,26.59 7.87,26.35 C374.2
N13800911: length 2.4
  BOTTOM w0.076: C373.1 13.72,29.43
  BOTTOM w0.25: U33.43 13.24,28.95 13.72,29.43 14.43,29.43 C375.2
N13800959: length 1.4
  BOTTOM w0.076: R6548.2 8.27,25.93
  BOTTOM w0.25: 8.27,25.93 8.29,25.95 U33.33
N13800993: length 1.4
  BOTTOM w0.076: R6548.1 8.27,25.3
  BOTTOM w0.25: 8.27,25.3 8.38,25.3 8.53,25.45 U33.32
N13800997: length 1.5
  BOTTOM w0.1: C113.1 10.22,29.21 10.74,28.7 U33.38
N13801001: length 1.5
  BOTTOM w0.1: U33.39 11.24,28.67 10.84,29.06 C114.1
N13801143: length 16.9
  INNER LAYER 5 w0.3: v3(8.86,21.71) 8.91,21.66 9.16,21.66 9.91,22.41 v3(15.31,22.41)
  INNER LAYER 8 w0.3: v3(15.31,22.41) 15.49,22.41 16.15,23.07 v1(18.06,23.07) ; v3(8.86,21.71) 8.71,21.71 v1(8.56,21.86)
  BOTTOM w0.076: C384.1 v1(18.06,23.07) ; 17.4,23.07 17.42,23.05 C381.1 ; C383.1 8.58,22.66
  BOTTOM w0.22: v1(18.06,23.07) 17.4,23.07 16.95,23.52 16.95,24.21 16.71,24.45 U33.7
  BOTTOM w0.25: U33.29 9.09,23.95 8.61,23.47 8.61,23 8.58,22.96 8.58,22.66
  BOTTOM w0.3: 8.58,22.66 8.58,22.22 8.56,22.21 v1(8.56,21.86) C453.1 7.56,21.8 B3.1
N13801371: length 38.9
  INNER LAYER 8 w0.3: v1(7.56,24.7) 7.25,25.02 7.25,28.02 8.01,28.79 8.01,29.01 ; 8.01,29.01 v1(11.56,29.01) 11.56,29.36 v1(11.5,29.42) ; 8.01,29.01 v1(8.01,29.17)
  INNER LAYER 8 w0.4: 13.9,27.62 v2(13.5,27.22) ; 13.9,27.62 v3(13.9,27.57) 13.15,27.57 ; 13.9,27.62 14.34,28.05 14.34,28.59 15.17,29.42 v1(15.3,29.42) 15.61,29.42 v1(16.06,29.87) ; v2(13.5,27.22) 13.88,26.84 13.88,25.52 13.81,25.45 13.81,19.11 v2(14.23,18.68) ; v2(13.5,27.22) 13.15,27.57 ; 13.15,27.57 13.01,27.57 v1(11.56,29.01)
  BOTTOM w0.076: C361.1 11.53,29.42 ; C371.1 14.02,20.13 ; C370.1 14.02,19.51 ; C366.1 8.18,28.41
  BOTTOM w0.25: 11.53,29.42 11.53,29.14 11.74,28.93 ; 14.02,19.51 14.02,20.13 14.02,20.14 14.02,20.49 13.74,20.77 U33.17 ; U33.36 9.12,27.45 8.73,27.84 8.72,27.84 8.18,28.38 8.18,28.41 ; U33.31 7.81,24.95 v1(7.56,24.7) ; U33.45 14.24,28.7 14.38,28.84 14.71,28.84 15.3,29.43 15.32,29.43
  BOTTOM w0.3: 8.18,28.41 8.18,29.01 v1(8.01,29.17) ; v1(14.28,18.73) 14.02,19 14.02,19.51
  BOTTOM w0.4: 11.53,29.42 11.74,29.2 U33.40 ; 15.32,29.43 15.62,29.43 v1(16.06,29.87) 16.32,29.61 16.95,29.61 B2.1
N13801403: length 1.6
  BOTTOM w0.076: U33.48 15.74,28.34 15.86,28.46 16.86,28.46 TP27.1
N13801411: length 1.4
  BOTTOM w0.076: 15.24,28.39 15.76,28.91 TP26.1
  BOTTOM w0.1: 15.24,28.39 U33.47
N13802455: length 6.3
  BOTTOM w0.3: C6405.1 25.24,45.59 L36.1 ; C6405.1 26.67,46.11 R6546.1 ; C6405.1 26.67,45.56 26.41,45.3
  BOTTOM w0.6: 26.41,45.3 26.41,44.97 25.77,44.33 C6233.1 25.77,44.17 25.35,43.75 25.35,42.73 B34.2
N13802681: length 4
  BOTTOM w0.6: 26.89,47.23 26.89,48.84 B35.1 26.89,48.98 25.05,48.98 L36.2
N13806908: length 5.5
  INNER LAYER 8 w0.15: v2(12.53,8.63) 12.46,8.56 9.5,8.56 9.22,8.28 8.76,7.82 v1(8.76,7.54)
  INNER LAYER 9 w0.15: v1(13.03,8.43) 12.73,8.43 v2(12.53,8.63)
  BOTTOM w0.15: v1(8.76,7.54) 8.76,7.8 8.7,7.86 8.7,7.87 ; v1(13.03,8.43) 13.13,8.34 R231.2
N13806920: length 10.1
  INNER LAYER 8 w0.15: v2(8.78,6.43) 8.88,6.53 9.73,6.53 10.95,7.75 12.88,7.75 v1(12.98,7.65)
  INNER LAYER 9 w0.15: v2(8.78,6.43) 8.78,6.16 v1(8.73,6.11)
  BOTTOM w0.076: C394.1 13.58,7.65
  BOTTOM w0.15: v1(12.98,7.65) 13.58,7.65 13.77,7.83 14.68,7.83 15.08,8.23 D31.1 16.07,8.41 C395.1 16.35,8.66 16.37,8.66 16.46,8.75 16.46,8.77 16.88,9.18 B4.1
N14025873: length 4.9
  INNER LAYER 9 w0.1: v1(3.51,38.71) 3.21,39.01 3.21,41.21 3.41,41.41 v1(3.41,41.51)
  BOTTOM w0.1: BTTN5.4 3.69,37.15 L3712.2 ; v1(3.41,41.51) 3.69,41.79 BTTN5.3
  vias: v1(3.49,42.27) v1(3.48,41.9) v1(3.44,38.3) v1(3.41,37.93) v1(3.89,41.91) v1(3.9,41.52) v1(3.86,38.42) v1(3.83,38) v1(3.91,42.27) v1(3.92,38.91)
N14050811: length 6.1
  BOTTOM w0.076: v1(3.51,17.28) 3.7,17.1 BTTN3.3 3.75,17.07 L3710.2
  BOTTOM w0.25: BTTN3.4 4.71,14.43 4.71,15.88 3.7,16.9 BTTN3.3
  vias: v1(3.49,16.89) v1(3.49,16.53) v1(3.47,13.68) v1(3.45,13.31) v1(3.45,12.98) v1(3.88,16.87) v1(3.85,13.66) v1(3.88,13.29) v1(3.83,12.95) v1(3.91,17.29) v1(3.92,16.5)
N14316805: length 36.5
  TOP w0.3: Q2711.3 v6(30.46,34.76)
  INNER LAYER 3 w0.3: v6(30.46,34.76) 28.06,34.76 v3(27.26,35.56) ; v3(10.56,43.16) 11.36,42.36 11.36,41.16 9.18,38.98 9.14,38.98 9.14,37.73 v3(9.66,37.21)
  INNER LAYER 5 w0.3: v3(9.66,37.21) 9.66,36.86 10.56,35.96 26.86,35.96 v3(27.26,35.56)
  INNER LAYER 8 w0.3: v3(10.56,43.16) 10.46,43.16 8.76,44.86 v1(8.76,47.76)
N14502607: length 8.6
  BOTTOM w1: 32.99,40.67 32.99,40.38 32.05,39.43 v1(31.41,39.43) ; 33.25,40.67 33.25,46.63 32.99,46.89
  vias: v1(31.05,39.41) v1(31.43,47.38) v1(32,47.46) v1(31.95,40.06) v1(32.34,40.09) v1(32.34,39.73) v1(32.34,39.35) v1(32.64,49.39) v1(32.64,48.81) v1(32.64,48.29) v1(32.61,47.75) v1(32.75,40.05) v1(32.73,39.7) v1(32.77,39.32) v1(33.14,49.32) v1(33.16,48.8) v1(33.17,48.21) v1(33.19,47.66)
N15879819: length 4
  BOTTOM w0.3: L3703.2 14.34,32.01 U4619.1
N15880146: length 22.5
  INNER LAYER 8 w0.3: 18.01,35.81 18.06,35.76 v1(18.06,32.5) ; 18.01,35.81 9.96,35.81 v1(9.71,35.56) ; 18.01,35.81 v1(22.36,35.81)
  BOTTOM w0.076: C6272.1 25.09,33.57
  BOTTOM w0.3: U6834.9 23.66,34.1 C6299.1 ; C6299.1 24.36,34.42 24.36,34.3 25.09,33.57 25.11,33.57 ; C6299.1 24.17,35 23.36,35.81 v1(22.36,35.81) ; R6581.1 9.61,35.47 U4619.5
N15881033: length 2.6
  BOTTOM w0.3: R6581.2 8.66,35.4 U4619.4 8.62,34.45 R6580.1
N15881893: length 3.9
  BOTTOM w0.076: R6578.2 11.86,33.1
  BOTTOM w0.3: U4619.3 8.66,32.41 9.35,33.1 11.86,33.1
N15883520: length 11.2
  BOTTOM w0.076: R6634.1 17.43,33.11 ; R6635.1 17.42,33.7 ; R6628.1 18.05,33.71
  BOTTOM w0.15: 21.31,34.32 20.18,35.46 19.96,35.46 L3709.2 ; 21.31,34.32 21.47,34.32 ; 21.31,34.32 21.31,34.11 21.16,33.96 U6834.4 ; 22.16,34.35 C6301.2 22.66,34.37 U6834.7 ; 22.16,34.35 U6834.6 ; 22.16,34.35 22.13,34.32 21.47,34.32 ; 21.47,34.32 21.66,34.12 U6834.5
  BOTTOM w0.3: L3709.2 18.27,34.97 18.05,34.75 18.05,33.71 17.43,33.71 17.42,33.7 17.43,33.7 17.43,33.11
N15883653: length 1.1
  BOTTOM w0.15: U6834.8 23.16,34.47 C6301.1
N15883704: length 2
  BOTTOM w0.076: R6626.1 18.71,32.49
  BOTTOM w0.3: C6302.2 18.71,31.81 18.71,32.49 18.86,32.49 19.06,32.69 19.76,32.69
N15884895: length 2.3
  BOTTOM w0.076: R6626.2 18.71,33.1 18.69,33.11 ; R6642.2 18.06,33.1 18.07,33.11
  BOTTOM w0.3: 18.06,33.12 18.07,33.11 18.97,33.11 19.41,33.56 U6834.2
N15885073: length 2.3
  INNER LAYER 9 w0.076: v1(25.16,30.16) 24.8,30.52 23.43,30.52 v1(23.16,30.26)
N15887049: length 2.8
  BOTTOM w0.076: R6628.2 18.68,33.71
  BOTTOM w0.3: 18.68,33.71 19.16,34.2 20.53,34.2 20.66,34.06 U6834.3
N15888229: length 16.7
  INNER LAYER 8 w0.8: v1(22.46,36.76) 22.51,36.76 23.21,36.06 23.21,29.41 23.11,29.3 v1(23.11,28.86)
  BOTTOM w0.22: 22.52,29.51 23.11,28.92 v1(23.11,28.86) ; 22.52,29.51 22.26,29.51 ; 22.52,29.51 22.66,29.65 v1(22.66,30.26) ; 22.26,29.51 21.88,29.51 21.66,29.73 v1(21.66,30.26) ; 22.26,29.51 22.16,29.61 v1(22.16,30.26) ; v1(24.02,28.91) 23.16,28.91 v1(23.11,28.86) ; v1(23.11,28.86) 22.96,28.72 C6305.1 23.91,26.51 D3853.1
  vias: v1(21.66,29.76) v1(22.16,36.76) v1(22.16,29.76) v1(22.21,37.16) v1(22.61,37.16) v1(22.76,36.76) v1(22.71,29.76) v1(22.96,37.16) v1(23.06,36.56) v1(23.06,29.31) v1(23.11,36.91) v1(23.51,29.36) v1(23.61,29.06) v1(23.61,28.71) v1(23.91,29.41) v2(22.16,36.76) v2(22.21,37.16) v2(22.61,37.16) v2(22.76,36.76) v2(22.96,37.16) v2(23.06,36.56) v2(23.06,29.31) v2(23.11,36.91) v2(23.51,29.36) v2(23.61,29.06) v2(23.61,28.71) v2(23.91,29.41)
N15889567: length 3.7
  BOTTOM w0.2: U6834.17 21.16,29.86 20.83,29.53 20.68,29.53 R6631.1 ; R6630.2 20.13,28.4 R6631.1 ; R6631.1 20.28,28.83 C6310.2
N15892910: length 1.2
  BOTTOM w0.076: C6306.2 25.11,32.27
  BOTTOM w0.15: 24.06,32.69 24.7,32.69 25.11,32.27
N15893880: length 1.6
  BOTTOM w0.076: R6632.2 18.63,30.41
  BOTTOM w0.22: 18.63,30.41 20.01,30.41 U6834.19
N15895046: length 0.6
  BOTTOM w0.076: 18.46,28.5 R6633.1 ; C6307.2 17.86,28.5
  BOTTOM w0.15: 17.86,28.5 18.46,28.5
N15896834: length 3.4
  BOTTOM w0.076: C6308.2 18.63,29.81 ; 18.53,29.12 18.5,29.1 R6633.2
  BOTTOM w0.22: 18.63,29.81 18.68,29.75 ; 18.68,29.75 18.78,29.66 20.31,29.66 20.66,30.01 U6834.18 ; 18.68,29.75 18.56,29.64 18.56,29.16 18.53,29.12 18.46,29.12
N15911517: length 1.3
  BOTTOM w0.076: 16.8,33.7 16.81,33.7 R6635.2 ; R6634.2 16.82,33.11 16.8,33.12 ; C6309.1 16.8,32.51
  BOTTOM w0.3: 16.8,33.7 16.8,33.7 16.8,32.51
N15911869: length 1.7
  BOTTOM w0.076: C6310.1 21.48,28.78
  BOTTOM w0.2: C6310.1 22.2,28.83 R6636.2
  BOTTOM w0.22: R6630.1 21.38,28.09 21.48,28.19 21.48,28.78
N16075101: length 1.7
  INNER LAYER 8 w0.076: 25.55,8.95 25.19,8.58 25.19,8.42 v1(25.1,8.42)
  INNER LAYER 8 w0.1: v8(25.59,9.29) 25.55,9.25 25.55,8.95
  BOTTOM w0.076: v1(25.1,8.42) 25.1,8.25 25.15,8.2 R124.1
N16803003: length 1.2
  INNER LAYER 3 w0.076: v3(37.28,25.25) 37.5,25.46 v6(38,25.46)
  INNER LAYER 8 w0.076: v1(37.62,25.12) 37.41,25.12 v3(37.28,25.25)
N16803691: length 9.6
  TOP w0.076: 38.5,20.96 38.17,21.3 37.24,21.3 37.09,21.15 37.09,20.1 37.89,19.3 v5(38.05,19.3)
  INNER LAYER 2 w0.076: v5(41.63,16.56) 41.28,16.91 38.93,16.91 38.64,17.19 38.64,18.71 v5(38.05,19.3)
N16803695: length 9.2
  TOP w0.076: v5(38.08,18.91) 37.91,18.91 36.94,19.88 36.94,21.28 37.12,21.46 38.5,21.46
  INNER LAYER 2 w0.076: v5(40.98,16.59) 40.83,16.75 38.88,16.75 38.48,17.14 38.48,18.51 v5(38.08,18.91)
N17038564: length 9
  TOP w0.076: R6654.2 27.55,48.06 28.01,48.06 28.31,47.76 28.31,46.56 29.56,45.31 29.56,42.41 29.31,42.16 29.01,42.16 28.56,41.71 28.05,41.71
N17038587: length 9.1
  TOP w0.076: 28.05,42.81 28.56,42.81 29.01,42.36 29.23,42.36 29.36,42.49 29.36,43.35 arc(29.34,43.41) 29.27,43.44 29.2,43.44 arc(29.11,43.53) 29.2,43.62 29.27,43.62 arc(29.36,43.7) 29.27,43.79 29.2,43.79 arc(29.11,43.88) 29.2,43.97 29.27,43.97 arc(29.34,43.99) 29.36,44.06 29.36,45.23 28.11,46.48 28.11,47.68 27.93,47.86 27.55,47.86 R6653.2
N17045642: length 3.1
  TOP w0.076: 28.05,36.21 30.31,36.21 TP97.1
N17046059: length 5.7
  TOP w0.2: TP98.1 32.71,17.36 29.91,17.36 28.96,16.41 28.05,16.41
N17057745: length 2.9
  TOP w0.076: 30.95,18.66 R6657.2
  TOP w0.2: 28.05,18.61 30.9,18.61 30.95,18.66
N17108422: length 2.2
  TOP w0.2: 28.05,27.41 30.16,27.41 TP102.1
N17108433: length 2.2
  TOP w0.2: 28.05,28.51 30.16,28.51 TP103.1
N17108458: length 2.2
  TOP w0.2: TP104.1 30.16,29.61 28.05,29.61
N17108467: length 2.2
  TOP w0.2: 28.05,30.71 30.16,30.71 TP105.1
N17108508: length 2.6
  TOP w0.076: 30.36,24.65 R6536.1
  TOP w0.1: 28.05,24.11 29.83,24.11 30.36,24.65
N17215166: length 9.2
  INNER LAYER 8 w0.076: v1(10.29,14.88) 10.48,14.88 10.73,15.14 11.28,15.14 11.42,15.27 11.55,15.27 13.26,16.99 13.38,16.99 14.89,16.99 15.83,17.93 v1(15.83,18.02)
  BOTTOM w0.076: Y2.3 17.45,17.92 15.94,17.92 v1(15.83,18.02)
N17215182: length 7.4
  INNER LAYER 8 w0.076: v1(15.83,17.43) 15.78,17.38 15.5,17.38 14.95,16.83 13.32,16.83 11.61,15.12 11.48,15.12 11.34,14.98 10.92,14.98 v1(10.8,14.87)
  BOTTOM w0.076: C417.1 15.83,17.4 16.6,17.4 Y2.1
N17221264: length 3.6
  INNER LAYER 8 w0.3: v1(17.67,12.68) 17.67,14.36 v1(16.92,15.1)
  BOTTOM w0.076: R6685.1 16.57,15.78
  BOTTOM w0.3: 16.57,15.78 16.57,15.46 v1(16.92,15.1)
N17222220: length 52.2
  INNER LAYER 8 w0.25: v1(10.78,14.38) 11.29,14.38 11.64,14.73 11.77,14.73 12.23,15.2 12.4,15.2 13.03,15.83 14.07,15.83 ; v1(6.95,15.48) 7.17,15.26 9.2,15.26 v1(9.28,15.35) ; v2(11.38,12.98) 11.38,11.55 v1(10.88,11.05)
  INNER LAYER 8 w0.3: v1(10.88,11.05) 10.88,10.58 10.12,9.82 8.09,9.82 7.88,10.02 v1(7.88,10.83) 7.88,11.13 v1(7.73,11.28) 7.18,11.83 7.18,12.03 5.78,13.43 v2(5.78,14.03) 5.78,14.38 v2(5.83,14.43) ; v2(11.33,15.83) 12.11,16.61 12.11,18.1 ; v1(6.95,15.48) v1(6.95,16.08) 6.79,16.24 6.79,16.78 6.73,16.83 ; 6.73,16.83 8.43,18.53 9.68,18.53 9.95,18.27 9.95,18.27 ; 6.73,16.83 v1(6.48,16.83) ; 9.95,18.27 v1(9.98,18.27) 10,18.28 v1(10.53,18.28) 10.53,18.38 10.68,18.53 11.68,18.53 12.11,18.1 ; 9.95,18.27 9.72,18.04 9.72,17.52 10,17.24 10,17.17 10.24,16.93 10.24,16.56 10.29,16.52 10.29,15.68 10.28,15.68 v1(10.28,15.38) ; 12.11,18.1 12.47,18.1 v1(12.83,17.73) ; v1(14.12,15.78) 13.57,16.33 v1(13.48,16.33)
  INNER LAYER 9 w0.25: v1(11.78,13.38) 11.73,13.38 11.38,13.03 v2(11.38,12.98)
  INNER LAYER 9 w0.3: v1(11.28,15.38) 11.28,15.78 v2(11.33,15.83) ; v1(6.95,16.08) v1(6.95,15.48) 5.9,14.43 v2(5.83,14.43) 5.78,14.38 v2(5.78,14.03)
  BOTTOM w0.076: C6399.2 14.12,15.18 ; C6394.1 11.48,11.05 ; C6400.2 6.95,14.83 ; C6401.2 8.98,11.05
  BOTTOM w0.22: v1(9.98,18.27) 10.58,18.27
  BOTTOM w0.3: v1(6.95,16.08) 7.25,16.38 U6838.B10 ; v1(6.95,16.08) v1(6.95,15.48) 6.95,14.83 7,14.88 U6838.E10 ; v1(6.95,16.08) 6.95,16.38 C452.1 ; v1(7.73,11.28) 7.88,11.13 v1(7.88,10.83) 7.93,10.83 8.23,11.13 8.9,11.13 ; 8.9,11.13 8.78,11.25 U6838.K9 ; 8.9,11.13 8.98,11.05 ; v1(12.08,11.05) 11.48,11.05 ; 11.48,11.05 11.48,11.43 11.78,11.73 U6838.K3 ; 11.48,11.05 v1(10.88,11.05) ; U6838.E1 13.48,14.88 13.78,15.18 14.12,15.18 v1(14.12,15.78) ; v1(13.48,16.33) 13.33,16.48 13.33,17.23 v1(12.83,17.73)
N17233104: length 3
  INNER LAYER 9 w0.3: v1(14.12,11.98) 12.72,13.38 v1(12.28,13.38)
  BOTTOM w0.076: R6672.2 14.12,11.38
  BOTTOM w0.3: 14.12,11.38 v1(14.12,11.98)
N17251830: length 4.9
  INNER LAYER 8 w0.1: v1(15.38,13.28) 15.38,13.31 15.36,13.33 15.02,13.33 14.97,13.28 13.89,13.28 13.59,13.58 11.89,13.58 11.89,13.58 11.36,13.58 11.32,13.62 11.05,13.62 v1(10.78,13.88)
N17251848: length 4.7
  INNER LAYER 9 w0.1: v1(15.37,15.18) 15.02,14.83 13.73,14.83 13.01,14.11 12.02,14.11 12.02,14.1 11.51,14.1 11.28,14.33 v1(11.28,14.38)
N17253194: length 2.6
  INNER LAYER 8 w0.3: v1(10.78,13.38) 10.78,11.93 10.23,11.38 10.23,11.1 v1(10.18,11.05)
N17253197: length 2.3
  INNER LAYER 8 w0.25: v2(13.08,15.28) 13.43,15.28 v1(14.13,14.58)
  INNER LAYER 9 w0.25: v2(13.08,15.28) 12.83,15.03 12.43,15.03 v1(12.28,14.88)
N17253674: length 4.5
  INNER LAYER 8 w0.1: v1(15.38,13.98) 15.11,13.71 14.9,13.71 14.82,13.63 14.03,13.63 13.56,14.1 12.05,14.1 12.03,14.08 11.48,14.08 v1(11.28,13.88)
N17253745: length 10.3
  INNER LAYER 8 w0.1: v1(11.78,13.83) 11.84,13.88 13.54,13.88 13.96,13.46 14.9,13.46 14.97,13.53 15.53,13.53 15.63,13.43 15.63,11.73 v2(16.23,11.13)
  INNER LAYER 9 w0.1: v2(16.23,11.13) 17.58,9.78 18.78,9.78 v1(19.18,9.38)
N17256163: length 5.9
  INNER LAYER 5 w0.1: v3(10.02,12.21) 10.21,12.21 10.33,12.08 14.05,12.08 14.25,12.28 15.03,12.28 15.07,12.32 15.07,12.34 v3(15.07,12.34)
  INNER LAYER 8 w0.1: v1(10.28,12.38) 10.11,12.21 v3(10.02,12.21) ; v1(15.37,12.18) 15.22,12.34 v3(15.07,12.34)
N17264893: length 4.5
  BOTTOM w0.076: 13.36,18.27 13.38,18.29 C6376.2
  BOTTOM w0.3: U6838.A4 11.28,17.08 11.53,17.33 12.23,17.33 12.38,17.48 12.38,18.19 C6404.1 12.7,18.27 13.6,18.27 B33.2
N17436018: length 4.5
  INNER LAYER 9 w0.15: v1(12.28,13.86) 12.28,13.87 12.3,13.88 12.83,13.88 14.43,12.28 14.43,11.16 14.12,10.85 v1(14.12,10.78)
N17436514: length 4.4
  INNER LAYER 8 w0.1: v1(15.37,12.76) 15.15,12.98 13.94,12.98 13.59,13.33 11.24,13.33 11.24,13.34 v1(11.22,13.37)
N17437459: length 14.7
  INNER LAYER 5 w0.076: v3(8.88,11.08) 9.18,10.78 15.13,10.78 16.09,11.74 v3(16.09,11.77)
  INNER LAYER 8 w0.1: v3(8.88,11.08) 8.88,11.33 8.87,11.35 8.87,11.58 8.88,11.59 8.88,12.79 9.81,13.71 9.81,14.01 10.18,14.38 v1(10.28,14.38) ; v1(15.37,14.48) 16.06,13.8 16.06,11.78 16.09,11.78 v3(16.09,11.77)
N17438882: length 2.2
  INNER LAYER 8 w0.3: v1(9.14,11.46) 9.16,11.48 9.16,12.68 v1(9.32,12.84)
  BOTTOM w0.076: R6687.1 9.58,11.05
  BOTTOM w0.25: v1(9.14,11.46) 9.16,11.46 9.41,11.46 9.58,11.28 9.58,11.05
N17439003: length 2.2
  INNER LAYER 9 w0.076: v1(8.78,16.38) 8.67,16.38 8.23,16.82 8.23,18.22 v1(8.18,18.27)
N17439463: length 3.1
  BOTTOM w0.076: U6838.B1 13.18,15.98 13.73,15.98 13.98,16.23 14.93,16.23 15.37,15.8 15.37,15.78 R6689.1
N17439531: length 2.3
  INNER LAYER 9 w0.15: v1(9.78,16.38) 9.78,17.23 8.78,18.23 v1(8.78,18.28)
N17698423: length 1.2
  BOTTOM w0.6: B35.2 28.05,50.51 B9.1
N17709894: length 1.4
  BOTTOM w0.076: C113.2 10.22,30.63 R1.1 9.57,30.65 TP2.1
N17709914: length 1.5
  BOTTOM w0.076: TP6.1 11.6,30.65 R1.2 10.84,30.63 C114.2
N143167610: length 5.5
  INNER LAYER 9 w0.3: v1(7.01,41.45) 7.01,44.51 v1(8.71,46.21)

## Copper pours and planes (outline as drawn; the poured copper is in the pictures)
GND on TOP (solid shape): 3.19,16.1 2.77,16.1 2.77,19.07 3.19,19.07
GND on TOP (solid shape): 6.9,19.19 4.81,19.19 4.81,20.22 6.9,20.22
GND on TOP (solid shape): 7.09,13.69 4.68,13.69 4.68,15.82 7.09,15.82
GND on TOP (solid shape): 7.67,11.24 5.89,11.24 5.89,12.36 7.67,12.36
GND on TOP (solid shape): 10.86,11.26 9.13,11.26 9.13,12.35 10.86,12.35
GND on TOP (solid shape): 12.89,10.84 11.06,10.84 11.06,13.08 12.89,13.08
GND on TOP (solid shape): 16.23,10.87 14.41,10.87 14.41,13.15 16.23,13.15
GND on TOP (solid shape): 19.48,10.85 17.63,10.85 17.63,13.09 19.48,13.09
GND on TOP (solid shape): 22.83,10.8 21.02,10.8 21.02,13.02 22.83,13.02
GND on TOP (solid shape): 34.91,19.24 34.14,19.24 34.14,34.33 34.91,34.33
GND on TOP (solid shape): 37.36,17.2 34.16,17.2 34.16,17.92 37.36,17.92
GND on TOP (solid shape): 44.4,14.53 39.64,14.53 39.64,15.31 44.4,15.31
GND on TOP (solid shape): 48.38,14.52 46.46,14.52 46.46,15.31 48.38,15.31
GND on TOP (solid shape): 52.43,14.52 49.95,14.52 49.95,15.32 52.43,15.32
GND on TOP (solid shape): 62.29,15.33 61.52,15.33 61.52,30.66 62.29,30.66
GND on TOP (solid shape): 62.32,32.3 61.5,32.3 61.5,36.22 62.32,36.22
GND on TOP (solid shape): 69.1,18.24 67.95,18.24 67.95,19.63 69.1,19.63
GND on TOP (solid shape): 71.33,36.26 38.99,36.26 38.99,37.01 71.33,37.01
GND on TOP (solid shape): 79.16,38.46 78.46,38.46 78.46,43.71 79.16,43.71
